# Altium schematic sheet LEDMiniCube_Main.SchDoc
size A4
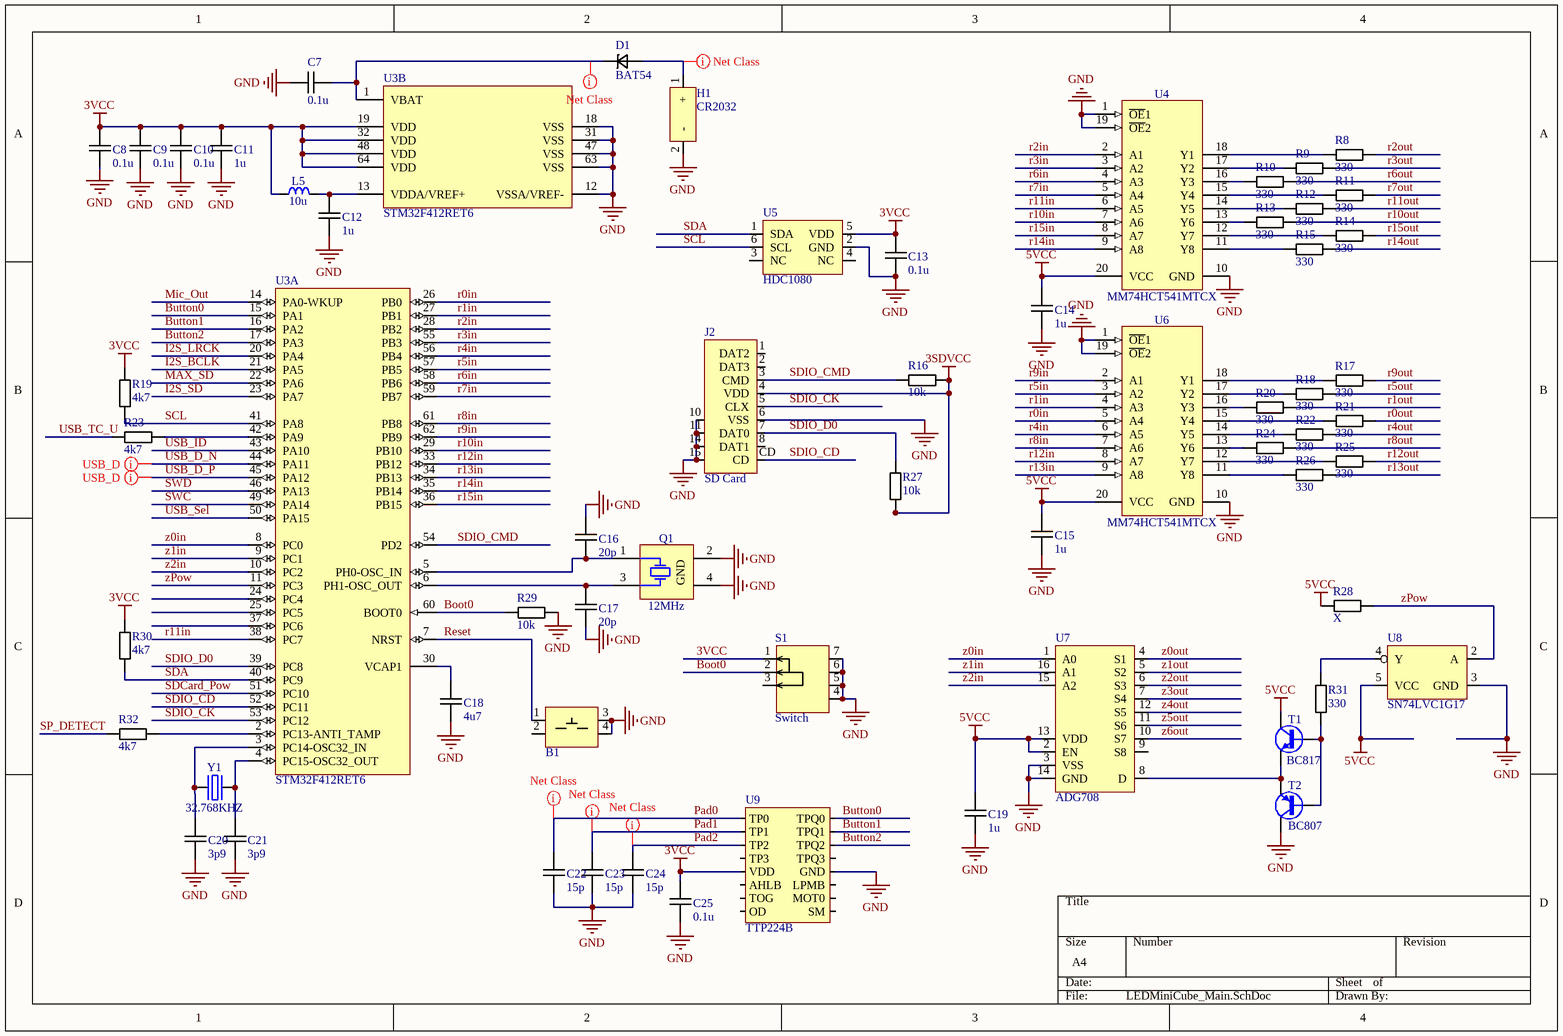
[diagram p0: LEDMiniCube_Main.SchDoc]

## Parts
B1  Button 5.2  [Button 5.2x5.2]  (value not drawn)
C7  0.1u  [CAPC1608L]
C8  0.1u  [CAPC1608L]
C9  0.1u  [CAPC1608L]
C10  0.1u  [CAPC1608L]
C11  1u  [CAPC1608L]
C12  1u  [CAPC1608L]
C13  0.1u  [CAPC1608L]
C14  1u  [CAPC2012L]
C15  1u  [CAPC2012L]
C16  20p  [CAPC1608L]
C17  20p  [CAPC1608L]
C18  4u7  [CAPC2012L]
C19  1u  [CAPC2012L]
C20  3p9  [CAPC1608L]
C21  3p9  [CAPC1608L]
C22  15p  [CAPC1608L]
C23  15p  [CAPC1608L]
C24  15p  [CAPC1608L]
C25  0.1u  [CAPC1608L]
D1  BAT54  [SOD-323F]
H1  CR2032  [Battery Holder cr2032]
J2  SD Card  [XUNPU TF-115]
L5  10u  [IND_ABRACON_AISC-0603]
Q1  12MHz  [XTAL_TXC_7M]
R8  330  [RESC2012L]
R9  330  [RESC2012L]
R10  330  [RESC2012L]
R11  330  [RESC2012L]
R12  330  [RESC2012L]
R13  330  [RESC2012L]
R14  330  [RESC2012L]
R15  330  [RESC2012L]
R16  10k  [RESC1608L]
R17  330  [RESC2012L]
R18  330  [RESC2012L]
R19  4k7  [RESC1608L]
R20  330  [RESC2012L]
R21  330  [RESC2012L]
R22  330  [RESC2012L]
R23  4k7  [RESC1608L]
R24  330  [RESC2012L]
R25  330  [RESC2012L]
R26  330  [RESC2012L]
R27  10k  [RESC1608L]
R28  X  [RESC1608L]
R29  10k  [RESC1608L]
R30  4k7  [RESC1608L]
R31  330  [RESC1608L]
R32  4k7  [RESC1608L]
S1  Switch  [TA-3524A-A1]
T1  BC817  [SOT95P230X110-3N]
T2  BC807  [SOT95P230X110-3N]
U3  STM32F412RET6  [STM-LQFP64_N]  (parts A,B of 2)
U4  MM74HCT541MTCX  [TSOP65P640X120-20N]
U5  HDC1080  [WSON HDC1080]
U6  MM74HCT541MTCX  [TSOP65P640X120-20N]
U7  ADG708  [TSOP65P640X110-16N]
U8  SN74LVC1G17  [SOT23-5AL]
U9  TTP224B  [SOP65P640-16L]
Y1  32.768KHZ  [XTAL_ABRACON_ABS09]

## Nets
3SDVCC: J2.4(VDD) R16.2 R27.1
3VCC: C8.2 C9.2 C10.2 C11.2 C13.2 C25.2 L5.1 R19.2 R30.2 S1.1 U3.19(VDD) U3.32(VDD) U3.48(VDD) U3.64(VDD) U5.5(VDD) U9.6(VDD)
5VCC: C14.2 C15.2 C19.2 R28.2 T1.3(C) U4.20(VCC) U6.20(VCC) U7.2(EN) U7.13(VDD) U8.5(VCC)
GND: B1.3 B1.4 C7.2 C8.1 C9.1 C10.1 C11.1 C12.1 C13.1 C14.1 C15.1 C16.2 C17.1 C18.1 C19.1 C20.1 C21.1 C22.1 C23.1 C24.1 C25.1 H1.2(-) J2.6(VSS) J2.10 J2.11 J2.14 J2.15 Q1.2(GND) Q1.4(GND) R29.2 S1.4 S1.5 S1.6 S1.7 T2.3(C) U3.12(VSSA/VREF-) U3.18(VSS) U3.31(VSS) U3.47(VSS) U3.63(VSS) U4.1(~{OE}1) U4.10(GND) U4.19(~{OE}2) U5.2(GND) U6.1(~{OE}1) U6.10(GND) U6.19(~{OE}2) U7.3(VSS) U7.14(GND) U8.3(GND) U9.10(GND)
Boot0: R29.1 S1.2 U3.60(BOOT0)
Button0: U3.15(PA1) U9.16(TPQ0)
Button1: U3.16(PA2) U9.15(TPQ1)
Button2: U3.17(PA3) U9.14(TPQ2)
I2S_BCLK: U3.21(PA5)
I2S_LRCK: U3.20(PA4)
I2S_SD: U3.23(PA7)
MAX_SD: U3.22(PA6)
Mic_Out: U3.14(PA0-WKUP)
Pad0: C22.2 U9.1(TP0)
Pad1: C23.2 U9.2(TP1)
Pad2: C24.2 U9.3(TP2)
r0in: U3.26(PB0) U6.5(A4)
r0out: R21.2
r1in: U3.27(PB1) U6.4(A3)
r1out: R20.2
r2in: U3.28(PB2) U4.2(A1)
r2out: R8.2
r3in: U3.55(PB3) U4.3(A2)
r3out: R9.2
r4in: U3.56(PB4) U6.6(A5)
r4out: R22.2
r5in: U3.57(PB5) U6.3(A2)
r5out: R18.2
r6in: U3.58(PB6) U4.4(A3)
r6out: R10.2
r7in: U3.59(PB7) U4.5(A4)
r7out: R11.2
r8in: U3.61(PB8) U6.7(A6)
r8out: R24.2
r9in: U3.62(PB9) U6.2(A1)
r9out: R17.2
r10in: U3.29(PB10) U4.7(A6)
r10out: R13.2
r11in: U3.38(PC7) U4.6(A5)
r11out: R12.2
r12in: U3.33(PB12) U6.8(A7)
r12out: R25.2
r13in: U3.34(PB13) U6.9(A8)
r13out: R26.2
r14in: U3.35(PB14) U4.9(A8)
r14out: R15.2
r15in: U3.36(PB15) U4.8(A7)
r15out: R14.2
Reset: B1.1 U3.7(NRST)
SCL: R19.1 U3.41(PA8) U5.6(SCL)
SDA: R30.1 U3.40(PC9) U5.1(SDA)
SDCard_Pow: U3.51(PC10)
SDIO_CD: J2.CD U3.52(PC11)
SDIO_CK: J2.5(CLX) U3.53(PC12)
SDIO_CMD: J2.3(CMD) R16.1 U3.54(PD2)
SDIO_D0: J2.7(DAT0) R27.2 U3.39(PC8)
SP_DETECT: R32.1
SWC: U3.49(PA14)
SWD: U3.46(PA13)
USB_D_N: U3.44(PA11)
USB_D_P: U3.45(PA12)
USB_ID: U3.43(PA10)
USB_Sel: U3.50(PA15)
USB_TC_U: R23.1
z0in: U3.8(PC0) U7.1(A0)
z0out: U7.4(S1)
z1in: U3.9(PC1) U7.16(A1)
z1out: U7.5(S2)
z2in: U3.10(PC2) U7.15(A2)
z2out: U7.6(S3)
z3out: U7.7(S4)
z4out: U7.12(S5)
z5out: U7.11(S6)
z6out: U7.10(S7)
zPow: R28.1 U3.11(PC3) U8.2(A)
NetC7_1: C7.1 D1.2 U3.1(VBAT)
NetC12_2: C12.2 L5.2 U3.13(VDDA/VREF+)
NetC16_1: C16.1 Q1.1(X) U3.5(PH0-OSC_IN)
NetC17_2: C17.2 Q1.3(X) U3.6(PH1-OSC_OUT)
NetC18_2: C18.2 U3.30(VCAP1)
NetC20_2: C20.2 U3.3(PC14-OSC32_IN) Y1.1(OSC1)
NetC21_2: C21.2 U3.4(PC15-OSC32_OUT) Y1.2(OSC2)
NetD1_1: D1.1 H1.1(+)
NetR8_1: R8.1 U4.18(Y1)
NetR9_1: R9.1 U4.17(Y2)
NetR10_1: R10.1 U4.16(Y3)
NetR11_1: R11.1 U4.15(Y4)
NetR12_1: R12.1 U4.14(Y5)
NetR13_1: R13.1 U4.13(Y6)
NetR14_1: R14.1 U4.12(Y7)
NetR15_1: R15.1 U4.11(Y8)
NetR17_1: R17.1 U6.18(Y1)
NetR18_1: R18.1 U6.17(Y2)
NetR20_1: R20.1 U6.16(Y3)
NetR21_1: R21.1 U6.15(Y4)
NetR22_1: R22.1 U6.14(Y5)
NetR23_2: R23.2 U3.42(PA9)
NetR24_1: R24.1 U6.13(Y6)
NetR25_1: R25.1 U6.12(Y7)
NetR26_1: R26.1 U6.11(Y8)
NetR31_1: R31.1 T1.1(B) T2.1(B)
NetR31_2: R31.2 U8.4(Y)
NetR32_2: R32.2 U3.2(PC13-ANTI_TAMP)
NetT1_2: T1.2(E) T2.2(E) U7.8(D)

Not connected (* = marked no-connect by the designer): B1 2; J2 1(DAT2) 2(DAT3) 8(DAT1); S1 3; U3 24(PC4) 25(PC5) 37(PC6); U5 3(NC) 4(NC); U7 9(S8); U9 4(TP3) 5(AHLB) 7(TOG) 8(LPMB) 9(MOT0) 11(OD) 12(SM) 13(TPQ3)

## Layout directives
differential pair: USB_D_N, USB_D_P
net class Clearance5; rule Clearance Constraint [Generic clearance = 0.15mm, and 30 value(s) for objects]: NetD1_1
net class Clearance5; rule Clearance Constraint [Generic clearance = 0.15mm, and 21 value(s) for objects]: NetC7_1
net class Clearance5: Pad0, Pad1, Pad2

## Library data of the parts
C7-C25 = Capacitor
D1 = Schotky
J2 = SD Card Socket
L5 = IND_390NH_5%_ABRACON_AISC-0603: Inductor
Q1 = XTAL_12MHZ_TXC_7M-12.000MAAJ-T: Crystal 4 pins 1=XTAL Control 2=GND3=XTAL 4=GND; Part Description: ±30ppm 18pF -20°C to +70°C  4 Pins, 3.2x2.5X0.8mm, SMD Sealing Crystal, 7M Series; Manufacturer: TXC CORPORATION; PressFit: No; Bonding: No
R8-R32 = Resistor
T1 = BC817: NPN Transistor; Part Number: BC817-40
T2 = BC807-25: PNP Transistor; Part Number: BC807-40
U3 = STM32F401RBT6: ARM Cortex-M4 32-bit MCU+FPU, 105 DMIPS, 128 kB Flash, 64 kB Internal RAM, 48 I/Os, 64-pin LQFP, -40 to 85 degC, Tray
U4 U6 = 74541: Octal Buffer/Line Driver with 3-State Outputs
U7 = ADG708: Part: ADG708BRUZ
U8 = SN74LVC1G04: Part: SN74LVC1G17DBVR
U9 = TTP224
Y1 = XTAL_32.768KHZ_ABRACON_ABS09-32.768KHZ-T: Quartz Crystal; Part Description: Tolerance: ±20ppm, Stability: ±5ppm, -40°C to +85°C, 12.5pF, SMD Low Profile Crystal, ABS09 Series; PressFit: No; Bonding: No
